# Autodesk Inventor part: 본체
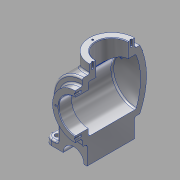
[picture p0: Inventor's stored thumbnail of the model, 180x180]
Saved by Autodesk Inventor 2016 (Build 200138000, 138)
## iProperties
Created: 2018-08
Part Number: 본체
Material: 알루미늄 6061
Document SubType Name: Modeling
Designer: Administrator
Density: 2.7 g/cm^3
Appearance: 알루미늄 - 평지
Mass: 1862.49 g
Surface Area: 1084.89 cm^2
Volume: 689.811 cm^3
Author: Administrator
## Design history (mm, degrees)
sketch "스케치5"
  geometry: L1 (-78.694, 82)-(132.474, 82); L2 (-60, 82)-(-60, 120); L3 (-60, 120)-(-48, 120); L4 (-48, 120)-(-48, 132); L5 (-48, 132)-(48.671, 132); L6 (0, 0)-(0, 191.791); L7 (-60, 82)-(60, 82); A1 r 116 centre (-56, 82) between (60, 82) and (48.671, 132)
  constraints: 14 end point, 3 perpendicular, 3 point on line, 2 point on circle, 2 vertical, 1 centre point, 1 collinear, 1 horizontal
  dimensions: "d18" = 164 diameter of L6.start L1; "d19" = 76 diameter of L3 L1; "d20" = 100 diameter of L5 L1; "d21" = 12 distance between parallel lines of L4 L2; "d22" = 108 distance from line of L7.end L4; "d23" = 116 radius of A1; "d35" = 48 distance between parallel lines of L4 L6
revolve "회전1" sketch "스케치5" stored, may be unused: angle "d25" = 90 deg
sketch "스케치7"
  geometry: L1 (0, 0)-(70, 0); L2 (70, 0)-(70, 10); L3 (70, 10)-(50, 10); L4 (50, 10)-(50, 37); L5 (50, 37)-(18.491, 82); L6 (18.491, 82)-(0, 82); L7 (0, 0)-(0, 21); L8 (0, 21)-(0, 15.105); L9 (-18.491, 82)-(0, 82); L10 (-50, 37)-(-18.491, 82); L11 (-50, 10)-(-50, 37); L12 (-70, 10)-(-50, 10); L13 (-70, 0)-(-70, 10); L14 (0, 0)-(-70, 0); C1 r 50 at (0, 82) reference
  constraints: 28 end point, 5 symmetric about line, 3 perpendicular, 2 horizontal, 1 point on line, 1 vertical
  dimensions: "d28" = 35 deg angle of L2 L5; "d29" = 10 distance of L1.end L2.end; "d30" = 20 distance between parallel lines of L2 L4; "d31" = 70 distance from line of L1.start L2; "d32" = 45 distance from line of L4.end L6
extrude "돌출1" join sketch "스케치7" stored distance "d33" = 80; taper "d34" = 0 deg
sketch "스케치10"
  geometry: L1 (-27.818, 82)-(126.267, 82); L2 (-60, 120)-(-48, 120) reference; L3 (-48, 132)-(48.671, 132) reference; L4 (-48, 32)-(-48, 132) reference; L5 (-60, 110)-(-38, 110); L6 (42.163, 122)-(-38, 122); L7 (-38, 122)-(-38, 110); L8 (-60, 110)-(-60, 82); L9 (-60, 82)-(50, 82); L10 (-60, 44)-(-60, 120) reference; A1 r 116 centre (-56, 82) between (48.671, 32) and (48.671, 132) reference; A2 r 106 centre (-56, 82) between (50, 82) and (42.163, 122); 1 further point
  constraints: 12 end point, 2 collinear, 2 point on circle, 1 centre point, 1 horizontal, 1 parallel, 1 perpendicular, 1 point on line
  dimensions: "d36" = 164 diameter of point (0, 0) L1; "d38" = 10 distance between parallel lines of L2 L5; "d39" = 10 distance between parallel lines of L3 L6; "d40" = 10 radial gap between concentric circles of A1 A2; "d42" = 22 distance between parallel lines of L7 L10
revolve "회전2" sketch "스케치10" stored, may be unused: angle "d43" = 90 deg
node "작업 평면1"
sketch "스케치11"
  geometry: L1 (50, -48)-(-50, -48) reference; L2 (0, -48)-(0, 92.364); C1 r 38 at (0, 2)
  constraints: 2 end point, 1 centre point, 1 midpoint, 1 vertical
  dimensions: "d45" = 76 diameter of C1; "d109" = 50 distance from line of L1 C1.centre; "d110" = 0 distance from line of C1.centre L2
extrude "돌출2" join sketch "스케치11" stored distance "d46" = 80; taper "d47" = 0 deg
hole "구멍1" diameter "d50" = 54; stored, may be unused: countersink angle "d56" = 90 deg, drill point angle "d58" = 118 deg; dims "d51" = 23.673, "d52" = 0.62479, "d53" = 66.139, "d54" = 4, "d55" = 2, "d57" = 8, "d59" = 10, "d60" = 10
sketch "스케치12"
  geometry: L1 (-70, 0)-(70, 0) reference; C1 r 17.5 at (-22.5, 0); C2 r 12.5 at (27.5, 0); 1 further point
  constraints: 2 centre point, 2 point on line
  dimensions: "d61" = 22.5 distance of point (0, 0) C1.centre; "d62" = 27.5 distance of point (0, 0) C2.centre; "d63" = 35 diameter of C1; "d64" = 25 diameter of C2
extrude "돌출3" cut sketch "스케치12" stored distance "d65" = 80; taper "d66" = 0 deg
sketch "스케치13"
  geometry: C1 r 2 at (0, 32.5); C2 r 28 at (0, 0) reference; 1 further point
  constraints: 1 centre point, 1 vertical alignment
  dimensions: "d67" = 32.5 distance of C2.centre C1.centre; "d68" = 4 diameter of C1
hole "구멍2" sketch "스케치13" at (0, 32.5) diameter "d69" = 3.242; stored, may be unused: countersink angle "d73" = 90 deg, drill point angle "d75" = 118 deg; dims "d70" = 8, "d71" = 4, "d72" = 2, "d74" = 10
sketch "스케치14"
  geometry: C1 r 2 at (0, 32.5); C2 r 27 at (0, 0) reference; C3 r 38 at (0, 0) reference; 1 further point
  constraints: 1 centre point, 1 vertical alignment
  dimensions: "d80" = 4 diameter of C1; "d111" = 32.5 distance of C2.centre C1.centre
hole "구멍3" sketch "스케치14" at (0, 32.5) diameter "d81" = 3.242; stored, may be unused: countersink angle "d85" = 90 deg, drill point angle "d87" = 118 deg; dims "d82" = 8, "d83" = 4, "d84" = 2, "d86" = 10
fillet "모깎기1" dims "d91" = 10
fillet "모깎기2" dims "d92" = 3
hole "구멍4" diameter "d95" = 8; stored, may be unused: countersink angle "d99" = 90 deg, drill point angle "d101" = 118 deg; dims "d93" = 10, "d94" = 10, "d96" = 8, "d97" = 4, "d98" = 2, "d100" = 10
fillet "모깎기3" dims "d102" = 3
fillet "모깎기4" dims "d103" = 3
fillet "모깎기5" dims "d104" = 3
chamfer "모따기1" distance "d105" = 1; stored, may be unused: second distance "d106" = 2, angle "d107" = 45 deg
node "작업 평면3"
sketch "스케치18"
  geometry: C1 r 50 at (0, 82) reference; C2 r 32.5 at (0, 82); 1 further point
  constraints: 1 centre point, 1 coincident, 1 other
  dimensions: "d113" = 65 diameter of C2
feature "엠보싱1" sketch "스케치18" dims "d18" = 164, "d19" = 76, "d20" = 100, "d21" = 12, "d22" = 108, "d23" = 116, "d35" = 48, "d114" = 0.5, "d115" = 0
sketch "스케치19"
  geometry: L1 (-121.591, 184.348)-(99.738, 184.348); L2 (99.738, 184.348)-(99.738, -9.806); L3 (99.738, -9.806)-(-121.591, -9.806); L4 (-121.591, -9.806)-(-121.591, 184.348); 1 further point
  constraints: 8 end point, 2 parallel, 1 horizontal, 1 perpendicular
extrude "돌출4" cut sketch "스케치19" stored distance "d116" = 10; taper "d117" = 0 deg
node "솔리드1"
pattern_circular "원형 패턴1" dims angle "d77" = 360 deg
pattern_circular "원형 패턴2" dims angle "d89" = 360 deg
mirror "대칭1"
mirror "대칭2"
other parameters: "d44" = 147, "d112" = 54
